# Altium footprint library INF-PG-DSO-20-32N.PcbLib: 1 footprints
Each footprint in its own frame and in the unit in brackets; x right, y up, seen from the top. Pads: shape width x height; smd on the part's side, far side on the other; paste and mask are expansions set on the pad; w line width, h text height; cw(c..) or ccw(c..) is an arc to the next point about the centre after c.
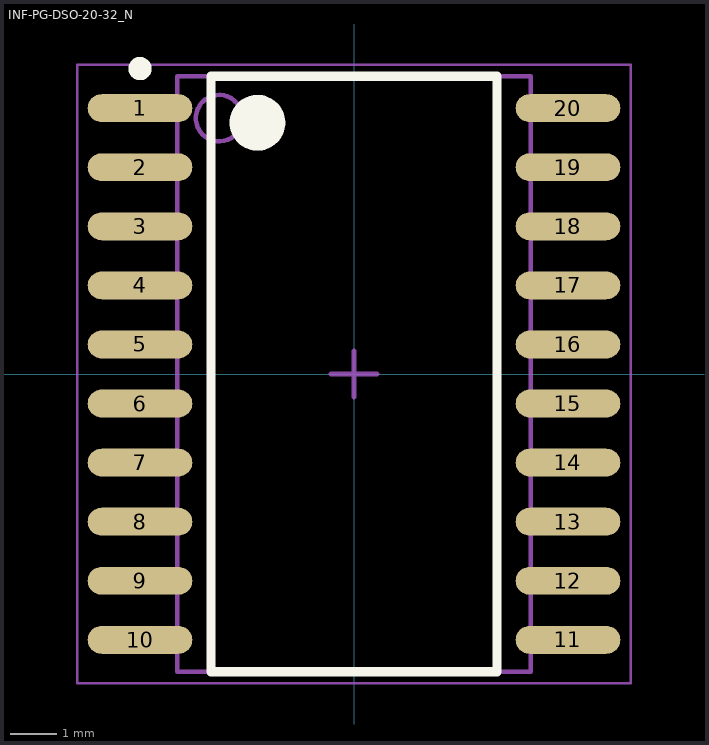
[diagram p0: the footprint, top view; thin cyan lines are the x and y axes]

## INF-PG-DSO-20-32_N [mm] "SOP, 20-Leads, Body 12.7x7.5mm, Pitch 1.27mm, IPC Medium Density"
height 2.65
pads (20):
  oval 2.25x0.6 smd: 1(-4.6,5.715) 2(-4.6,4.445) 3(-4.6,3.175) 4(-4.6,1.905) 5(-4.6,0.635) 6(-4.6,-0.635) 7(-4.6,-1.905) 8(-4.6,-3.175) 9(-4.6,-4.445) 10(-4.6,-5.715) 11(4.6,-5.715) 12(4.6,-4.445) 13(4.6,-3.175) 14(4.6,-1.905) 15(4.6,-0.635) 16(4.6,0.635) 17(4.6,1.905) 18(4.6,3.175) 19(4.6,4.445) 20(4.6,5.715)
Top Overlay:
  circle w0.25: c-4.6,6.565 r0.125
  circle w0.6: c-2.075,5.4 r0.3
  lines w0.2: -3.075,-6.4 -3.075,6.4 3.075,6.4 3.075,-6.4 -3.075,-6.4
Mechanical 13:
  circle w0.1: c-2.9,5.5 r0.5
  lines w0.1: -3.8,-6.4 -3.8,6.4 3.8,6.4 3.8,-6.4 -3.8,-6.4
Mechanical 15:
  lines w0.05: -5.95,-6.65 -5.95,6.65 5.95,6.65 5.95,-6.65 -5.95,-6.65
  lines w0.1: -0.5,0 0.5,0 ; 0,-0.5 0,0.5
3D body: height 2.65, standoff 0.1, extent -3.8,-6.4 3.8,6.4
